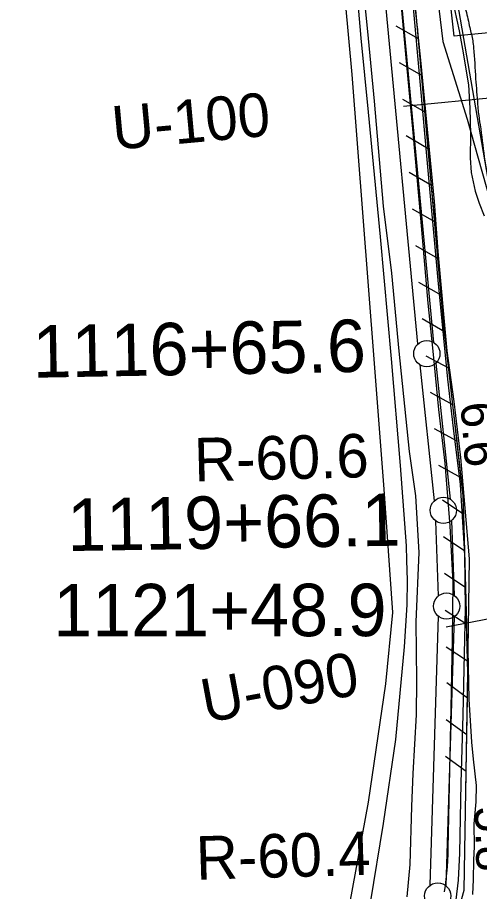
# Model space of a CAD drawing. Extents: x 3694830 to 3732949, y 415201 to 440970.
# Drawn here: x 3715252 to 3716134, y 423394 to 425061 of the extents above; entities that cross this region are included whole.
import ezdxf

# ---------------------------------------------------------------- set-up
doc = ezdxf.new("R2010")
doc.units = 0
for name, color, linetype in [('V-FLOD-BASE', 7, 'Continuous'), ('V-LEVE-TOET', 7, 'Continuous'), ('V-RAIL-TRAK', 7, 'Continuous'), ('V-RIVR-EDGE', 7, 'Continuous'), ('V-RIVR-RANG', 7, 'Continuous'), ('V-RIVR-RANG-IDEN', 7, 'Continuous'), ('V-RRAP-FSHR', 7, 'Continuous'), ('V-RRAP-RVMT', 7, 'Continuous'), ('V-SITE-VEGE', 7, 'Continuous'), ('V-SURV-IDEN', 7, 'Continuous'), ('V-SURV-LINE', 7, 'Continuous'), ('V-TOPO-MINR', 7, 'Continuous')]:
    doc.layers.add(name, color=color, linetype=linetype)

msp = doc.modelspace()

# ---------------------------------------------------------------- linework, layer by layer
at = {"layer": 'V-FLOD-BASE'}
msp.add_lwpolyline([(3716067.1, 423393.2), (3716068.7, 423405.1), (3716070.1, 423417), (3716071.3, 423428.9), (3716072.3, 423440.9), (3716073, 423452.9), (3716073.6, 423464.9), (3716074, 423476.8), (3716076.1, 423595.8), (3716079.6, 423743.8), (3716081.8, 423875.5), (3716083.3, 423982.3), (3716077.4, 424091.2), (3716067.9, 424210.8), (3716056.2, 424313.5), (3716045.5, 424418.3), (3716035.8, 424515.7), (3716021.4, 424678.2), (3716007, 424841.7), (3715993, 424990.9), (3715975.3, 425187.3)], dxfattribs=at)
at = {"layer": 'V-LEVE-TOET'}
for points in [[(3715995.5, 423384), (3716001.4, 423445.3), (3716004.5, 423556.3), (3716007.2, 423618.7), (3716013.5, 423730.7), (3716014.1, 423796.3), (3716013, 423908.4), (3716018.4, 424040.5), (3716012, 424148.4), (3716000.1, 424233.2), (3715980.6, 424424.7), (3715966.1, 424572.9), (3715950.4, 424701), (3715933.1, 424901.1), (3715920.6, 425034.4), (3715906, 425178.4), (3715887.5, 425350.9), (3715867.2, 425561.6), (3715849, 425772.2), (3715848.5, 425779.6), (3715835.1, 425981.7), (3715812, 426234.7)], [(3715917, 426019.1), (3715930.3, 425906.9), (3715943.8, 425771.9), (3715959.3, 425607.3), (3715971.2, 425464.5), (3715986.2, 425309.4), (3716005.4, 425100.9), (3716020.8, 424924.7), (3716032.8, 424789.7), (3716053.9, 424560), (3716072.8, 424371.1), (3716083.1, 424277.4), (3716096.4, 424170), (3716105.2, 424037.2), (3716105.9, 423933.5), (3716104.1, 423847.3), (3716101.9, 423731), (3716098.1, 423600.5), (3716095.3, 423466.7), (3716092.7, 423415.4), (3716088.7, 423377.9)]]:
    msp.add_lwpolyline(points, dxfattribs=at)
at = {"layer": 'V-RAIL-TRAK'}
for points in [[(3715607.7, 428367), (3715620.4, 428242.1), (3715640.5, 428016.7), (3715666.5, 427729.9), (3715694.5, 427434.5), (3715722.2, 427107.5), (3715752.2, 426798.4), (3715771.4, 426589.9), (3715794.3, 426310.5), (3715818.3, 426050.1), (3715838.3, 425800.4), (3715839.8, 425780), (3715844, 425726.3), (3715860.4, 425557), (3715875.7, 425376), (3715892.1, 425199.2), (3715907.4, 425021.4), (3715920.9, 424880.6), (3715944.1, 424642.5), (3715965.3, 424409.6), (3715982.5, 424206.4)], [(3715982.5, 424206.4), (3715993.8, 424053), (3715994.6, 424025.5), (3715995.3, 423987.4), (3715994.9, 423940.9), (3715989.9, 423860.5), (3715973.5, 423684.1), (3715949.8, 423523.5), (3715925.2, 423372.5), (3715898.5, 423224.7), (3715875.2, 423101.2), (3715856.2, 422993.5), (3715837.2, 422876.3), (3715819.3, 422774.9), (3715791.7, 422646.1)]]:
    msp.add_lwpolyline(points, dxfattribs=at)
at = {"layer": 'V-RIVR-EDGE'}
msp.add_spline([(3715510.2, 429495), (3715519.4, 429459.4), (3715532.6, 429419.7), (3715534.2, 429406), (3715534.6, 429397.9), (3715533.8, 429394.7), (3715530.1, 429389.8), (3715520.8, 429385.4), (3715520.4, 429383.8), (3715529.2, 429357.1), (3715587, 429194.8), (3715589.1, 429189.1), (3715589.8, 429179.8), (3715594.7, 429167.3), (3715599.5, 429156.7), (3715608.4, 429150.6), (3715608.4, 429143.8), (3715610.7, 429128.4), (3715615.6, 429112.2), (3715631.6, 429074.6), (3715650.1, 429029.2), (3715664.6, 428990.4), (3715673.8, 428948.3), (3715681.8, 428932.1), (3715694.7, 428908.6), (3715704.7, 428877), (3715710.7, 428847.5), (3715716.7, 428803.4), (3715725.1, 428773.5), (3715730.3, 428739.1), (3715736.6, 428685.3), (3715740.6, 428651.7), (3715742.6, 428635.1), (3715750.2, 428602), (3715756.2, 428579.3), (3715763.8, 428568), (3715770.3, 428560.7), (3715775.9, 428548.5), (3715779.5, 428526.3), (3715782.3, 428514.1), (3715787.1, 428503.6), (3715794.8, 428492.7), (3715802.4, 428486.6), (3715812.9, 428475.2), (3715818.2, 428463.1), (3715822.6, 428444.1), (3715822.9, 428427.1), (3715822.1, 428409.3), (3715816.4, 428393.5), (3715813.9, 428385.5), (3715810.2, 428364.9), (3715808.6, 428348.3), (3715810.1, 428326), (3715814.1, 428296.1), (3715814.9, 428282.4), (3715814.8, 428265.4), (3715814, 428246.4), (3715819.2, 428212), (3715825.5, 428176.8), (3715828.3, 428148.5), (3715834.3, 428123.4), (3715842.4, 428110), (3715849.6, 428100.3), (3715854, 428086.1), (3715854.8, 428064.7), (3715853.5, 428030.7), (3715846.1, 427990.7), (3715841.2, 427968.1), (3715841.2, 427956.4), (3715841.1, 427943.8), (3715851.6, 427910.2), (3715867.2, 427862.5), (3715873.6, 427835.8), (3715876, 427815.6), (3715876, 427799.4), (3715870.3, 427782), (3715868.6, 427769.5), (3715868.6, 427757.3), (3715873.7, 427723), (3715882.1, 427684.5), (3715885.3, 427654.6), (3715884, 427624.3), (3715879.5, 427578.6), (3715878.1, 427541.4), (3715878.8, 427496.5), (3715875.5, 427454.1), (3715874.6, 427412), (3715872.9, 427377.6), (3715869.6, 427336.4), (3715866.3, 427310.1), (3715865.8, 427291.5), (3715867.4, 427264), (3715873.3, 427234.5), (3715883.8, 427200.5), (3715895, 427166.5), (3715899.8, 427143.8), (3715900.2, 427120.8), (3715892.8, 427089.3), (3715886.7, 427071.1), (3715883.4, 427055.7), (3715883.4, 427037.9), (3715885.4, 427020.9), (3715899.8, 426986.1), (3715910.3, 426959), (3715917.1, 426933.5), (3715925.1, 426900.3), (3715927.9, 426873.7), (3715928.2, 426853), (3715928.1, 426806.5), (3715927.6, 426760.8), (3715929.5, 426734.1), (3715927, 426703.4), (3715921.7, 426671.5), (3715916.8, 426641.6), (3715917.1, 426618.5), (3715918.7, 426593.4), (3715921.4, 426562.3), (3715922.2, 426531.6), (3715931.7, 426461.6), (3715934, 426424.8), (3715934.8, 426396.5), (3715937.5, 426364.9), (3715941.4, 426303.9), (3715943.7, 426258.2), (3715946.1, 426223), (3715949.6, 426185.4), (3715954.7, 426102.9), (3715958.6, 426073.7), (3715967.4, 426016.7), (3715974.5, 425960.5), (3715974.9, 425934.2), (3715982.4, 425875.1), (3715988, 425832.7), (3715990.7, 425805.2), (3715996.3, 425788.6), (3716003.6, 425763.9), (3716005.5, 425745.3), (3716009.8, 425685.8), (3716015, 425646.2), (3716020.1, 425601.7), (3716024.1, 425552.7), (3716029.2, 425516.3), (3716032.8, 425488.4), (3716038.8, 425450.8), (3716039.9, 425423.3), (3716046.7, 425372.7), (3716051.1, 425349.3), (3716057.4, 425317.7), (3716059.8, 425289), (3716060.2, 425266.8), (3716063.7, 425234), (3716070.9, 425189.5), (3716078.1, 425159.6), (3716092.1, 425118.3), (3716107.4, 425074.2), (3716115, 425041.8), (3716120.6, 425016.3), (3716122.2, 425003), (3716126.1, 424943.9), (3716130, 424894.6), (3716131.2, 424880), (3716134.8, 424856.1), (3716142.7, 424795.1), (3716147.5, 424765.1), (3716151.9, 424739.6), (3716155.9, 424721.4), (3716163.1, 424703.2), (3716186, 424653.8), (3716195.7, 424627.1), (3716208.9, 424591.5), (3716230.2, 424544.1), (3716256.4, 424502), (3716274.1, 424469.2), (3716284.6, 424452.2), (3716301.1, 424424.7), (3716313.6, 424398.4), (3716323.6, 424368), (3716332.4, 424330.8), (3716336.4, 424302.9), (3716343.1, 424241.8), (3716348.3, 424203), (3716353.5, 424178.7), (3716357.5, 424163.3), (3716373.9, 424099.4), (3716379.4, 424058.5), (3716381.8, 424039.9), (3716383.8, 424027.8), (3716388.2, 424014.4), (3716400.6, 423964.7), (3716419.1, 423899.1), (3716425.5, 423869.6), (3716436.7, 423820.2), (3716441.9, 423786.6), (3716440.6, 423761.2), (3716435.3, 423741.4), (3716429.2, 423726.4), (3716425.1, 423722.8), (3716421.5, 423722.4), (3716417.8, 423723.6), (3716415.4, 423726), (3716420.3, 423737.8), (3716418.7, 423748.3), (3716417.1, 423757.2), (3716413.1, 423763.7), (3716404.2, 423765.7), (3716397.3, 423768.1), (3716386.4, 423771.4), (3716380, 423773.4), (3716373.1, 423775.1), (3716361.8, 423776.7), (3716353.7, 423774.7), (3716341.5, 423766.3), (3716329.3, 423744.9), (3716320.4, 423731.1), (3716311.8, 423697.2), (3716308.9, 423668.9), (3716306.4, 423653.3)], degree=3, dxfattribs=at)
at = {"layer": 'V-RIVR-RANG'}
for p, q in [((3715988.8, 424892), (3716805.2, 424968.9)), ((3716069.8, 423898.9), (3717032.8, 424080.6))]:
    msp.add_line(p, q, dxfattribs=at)
at = {"layer": 'V-RRAP-FSHR'}
for p, q in [((3716017.2, 425019.9), (3715974.8, 425044.3)), ((3716023.4, 424950.1), (3715981, 424974.5)), ((3716029.6, 424880.3), (3715987.2, 424904.7)), ((3716035.7, 424810.5), (3715993.4, 424834.9)), ((3716041.9, 424740.7), (3715999.5, 424765.1)), ((3716048.1, 424670.9), (3716005.7, 424695.3)), ((3716054.3, 424601.1), (3716011.9, 424625.5)), ((3716060.4, 424531.3), (3716018.1, 424555.7)), ((3716066.6, 424461.5), (3716024.2, 424485.9)), ((3716074.9, 424391.9), (3716031.9, 424415.2)), ((3716082.8, 424322.3), (3716039.9, 424345.6)), ((3716090.8, 424252.6), (3716047.8, 424276)), ((3716098.8, 424183), (3716055.8, 424206.3)), ((3716103.6, 424113.2), (3716062.9, 424140.2)), ((3716105.5, 424043.1), (3716064.7, 424070.1)), ((3716107.3, 423973.1), (3716066.5, 424000.1)), ((3716109.1, 423903), (3716068.3, 423930)), ((3716110.9, 423833), (3716070.1, 423860)), ((3716110.6, 423762.9), (3716071, 423791.7)), ((3716109.3, 423692.8), (3716069.8, 423721.6)), ((3716108.1, 423622.8), (3716068.6, 423651.5))]:
    msp.add_line(p, q, dxfattribs=at)
for points in [[(3714934.3, 430879.4), (3715310.8, 430066.4), (3715565.7, 429152.3), (3715743.6, 427937.5), (3715907.8, 426518.2), (3715968.2, 425803.5), (3716063.3, 425015.1), (3716110.2, 424867.2), (3716274.4, 424283), (3716360.4, 423797.4)], [(3716641.2, 420826), (3716497.1, 420943.7), (3716411.6, 421060.5), (3716364.3, 421170.5), (3716321.8, 421303.9), (3716285.1, 421373.8), (3716186.8, 421473.9), (3716066.8, 421590.9), (3715980.5, 421690), (3715930.3, 421828.7), (3715913.5, 421896.8), (3715879, 422073.9), (3715879.9, 422256.3), (3715873.1, 422428), (3715914, 422633.6), (3716031.3, 423135.8), (3716104.1, 423396.5), (3716111.4, 423811.5), (3716102.7, 424148.4), (3716065.6, 424473.1), (3715995.1, 425269.8), (3715894.2, 426351.1), (3715758.5, 427758)], [(3716017.2, 425019.9), (3716015.1, 425044)], [(3716023.4, 424950.1), (3716017.2, 425019.9)], [(3716029.6, 424880.3), (3716023.4, 424950.1)], [(3716035.7, 424810.5), (3716029.6, 424880.3)], [(3716041.9, 424740.7), (3716035.7, 424810.5)], [(3716048.1, 424670.9), (3716041.9, 424740.7)], [(3716054.3, 424601.1), (3716048.1, 424670.9)], [(3716060.4, 424531.3), (3716054.3, 424601.1)], [(3716066.9, 424461.5), (3716065.6, 424473.1), (3716060.4, 424531.3)], [(3716074.9, 424391.9), (3716066.9, 424461.5)], [(3716082.8, 424322.3), (3716074.9, 424391.9)], [(3716090.8, 424252.6), (3716082.8, 424322.3)], [(3716098.8, 424183), (3716090.8, 424252.6)], [(3716103.6, 424113.2), (3716102.7, 424148.4), (3716098.8, 424183)], [(3716105.5, 424043.1), (3716103.6, 424113.2)], [(3716107.3, 423973.1), (3716105.5, 424043.1)], [(3716109.1, 423903), (3716107.3, 423973.1)], [(3716110.9, 423833), (3716109.1, 423903)], [(3716110.6, 423762.9), (3716111.4, 423811.5), (3716110.9, 423833)], [(3716109.3, 423692.8), (3716110.6, 423762.9)], [(3716108.1, 423622.8), (3716109.3, 423692.8)], [(3716107.3, 423578.5), (3716108.1, 423622.8)]]:
    msp.add_lwpolyline(points, dxfattribs=at)
at = {"layer": 'V-RRAP-RVMT'}
msp.add_lwpolyline([(3716210.1, 425037.4), (3716085.4, 425025.2), (3716068.9, 425174.8), (3716062.3, 425174.1), (3716046, 425322.4), (3716043.2, 425322.1), (3716026, 425478.9), (3716030.6, 425479.4)], dxfattribs=at)
at = {"layer": 'V-SITE-VEGE'}
for points in [[(3716021.5, 424979.4), (3715999.4, 425193.8), (3715977, 425445.4), (3715950.2, 425736.5), (3715934, 425908.4), (3715908.5, 426166.2), (3715876.7, 426499.1), (3715845, 426839.7), (3715831.5, 426975.2), (3715810.2, 427186.6), (3715795.4, 427346.8), (3715779.6, 427565.1), (3715754.9, 427823.7)], [(3715187.1, 425538.8), (3715264.6, 425559.8), (3715277, 425565.9), (3715289.7, 425596.7), (3715293.5, 425677.1), (3715294, 425735.9), (3715306.9, 425785.3), (3715310.2, 425816.2), (3715313.4, 425825.4), (3715329, 425834.6), (3715452.6, 425818), (3715824.5, 425765.9), (3715829.9, 425692.2), (3715854.7, 425356.8), (3715868, 425180.7), (3715877.4, 425090.9), (3715890.3, 424952.3)], [(3716081.3, 425097.2), (3716094.7, 425035.2), (3716101.3, 425000.3), (3716112.3, 424932.1), (3716115, 424888), (3716116.1, 424837.7), (3716115.7, 424792.9), (3716117.8, 424765), (3716125.2, 424729.4), (3716132.7, 424706.9), (3716142.5, 424682.8)], [(3716120.7, 423388.1), (3716121.8, 423416.7), (3716122.9, 423453.8), (3716123.9, 423479.4), (3716123.5, 423522.7), (3716127, 423565.2), (3716128.1, 423596.1), (3716122.3, 423646.5), (3716118.7, 423679), (3716114.1, 423761), (3716111.8, 423854.6), (3716114.2, 424028.6), (3716098.1, 424221.4), (3716085.2, 424328.3), (3716072.1, 424425.1), (3716054.5, 424614.7), (3716047.6, 424709.9), (3716021.5, 424979.4)], [(3715890.3, 424952.3), (3715931.8, 424408.9), (3715951.2, 424161.2), (3715967.6, 423925.9), (3715954, 423789.8), (3715921, 423564.3), (3715842.9, 423138)]]:
    msp.add_lwpolyline(points, dxfattribs=at)
at = {"layer": 'V-SURV-LINE'}
for points in [[(3716016.2, 424438.2), (3715834.8, 426357.7)], [(3715864.6, 426360.6), (3716046.1, 424441)], [(3716047.6, 424139.1), (3716020.2, 424398.2)], [(3716050.1, 424401.4), (3716077.4, 424142.3)], [(3716055.1, 423957.7), (3716050.3, 424100.4)], [(3716080.3, 424101.4), (3716085.1, 423958.7)], [(3716039.5, 423405.8), (3716055.2, 423918.7)], [(3716085.1, 423917.8), (3716069.4, 423404.9)]]:
    msp.add_lwpolyline(points, dxfattribs=at)
for centre in [(3716033.1, 424419.7), (3716064.6, 424120.9), (3716070.8, 423938.2), (3716053.8, 423385.4)]:
    msp.add_circle(centre, 25, dxfattribs=at)
at = {"layer": 'V-TOPO-MINR'}
msp.add_lwpolyline([(3715985.9, 426095.6), (3716079.5, 425157.2), (3716236.8, 424248.7), (3716278.8, 423494.1), (3716279.2, 423484.3), (3716279.3, 423474.5), (3716279.2, 423464.7), (3716278.9, 423455), (3716272.7, 423329)], dxfattribs=at)

# ---------------------------------------------------------------- texts
at = {"layer": 'V-RIVR-RANG'}
for s, rotation, p in [('6.6', 274.2883, (3716097.2, 424325.6)), ('5.8', 271.5183, (3716124.6, 423555.6))]:
    msp.add_text(s, height=67, rotation=rotation, dxfattribs=at).set_placement(p)
at = {"layer": 'V-RIVR-RANG-IDEN'}
for s, rotation, p in [('U-100', 5.2433, (3715436.3, 424808.3)), ('R-60.6', 1.4338, (3715590.1, 424175.8)), ('U-090', 10.5433, (3715611, 423715.2)), ('R-60.4', 1.6751, (3715593.8, 423416.1))]:
    msp.add_text(s, height=83, rotation=rotation, dxfattribs=at).set_placement(p)
at = {"layer": 'V-SURV-IDEN'}
for s, rotation, p in [('1116+65.6', 1.0429, (3715281.9, 424373.7)), ('1119+66.1', 0.9406, (3715347.9, 424043.1)), ('1121+48.9', 0.0393, (3715320.5, 423880.5))]:
    msp.add_text(s, height=100, rotation=rotation, dxfattribs=at).set_placement(p)

doc.saveas('drawing.dxf')
